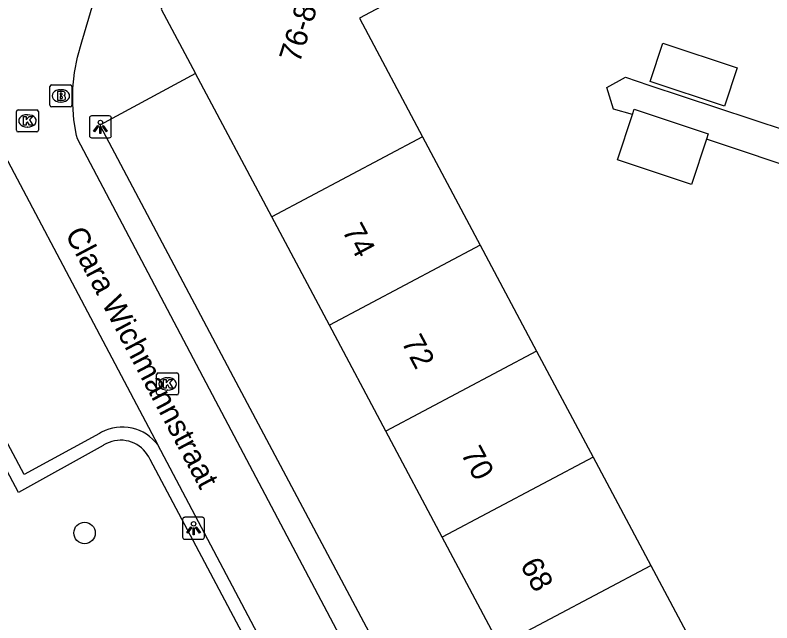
# Model space of a CAD drawing. Extents: x 160304 to 160954, y 383686 to 384161.
# Drawn here: x 160598.37 to 160632.85, y 383834.88 to 383862.58 of the extents above; entities that cross this region are included whole.
import ezdxf

# ---------------------------------------------------------------- set-up
doc = ezdxf.new("R2010")
doc.units = 0
for name, color, linetype in [('IMGEO_Boom', 7, 'Continuous'), ('IMGEO_Brandkraan', 7, 'Continuous'), ('IMGEO_Kolk', 7, 'Continuous'), ('IMGEO_Lichtpunt', 7, 'Continuous'), ('IMGEO_Openbare_ruimte_label', 7, 'Continuous'), ('IMGEO_Pand', 7, 'Continuous'), ('IMGEO_Pand_nummerreeks', 7, 'Continuous'), ('IMGEO_Rijbaan_lokaal_open', 7, 'Continuous'), ('IMGEO_Voetpad_open', 7, 'Continuous')]:
    doc.layers.add(name, color=color, linetype=linetype)

msp = doc.modelspace()

# ---------------------------------------------------------------- linework, layer by layer
at = {"layer": 'IMGEO_Boom'}
msp.add_circle((160601.533, 383838.982), 0.489, dxfattribs=at)
at = {"layer": 'IMGEO_Brandkraan'}
for p, q in [((160599.952, 383858.474), (160599.952, 383859.326)), ((160600.027, 383859.4), (160600.879, 383859.4)), ((160600.953, 383859.326), (160600.953, 383858.474)), ((160600.44, 383859.18), (160600.465, 383859.18)), ((160600.463, 383858.62), (160600.438, 383858.62)), ((160600.879, 383858.4), (160600.027, 383858.4))]:
    msp.add_line(p, q, dxfattribs=at)
for points in [[(160599.952, 383858.474), (160599.952, 383859.326)], [(160600.027, 383859.4), (160600.879, 383859.4)], [(160600.953, 383859.326), (160600.953, 383858.474)], [(160600.3, 383859.1), (160600.3, 383858.7), (160600.513, 383858.7)], [(160600.531, 383859.1), (160600.3, 383859.1)], [(160600.479, 383859.019), (160600.425, 383859.019), (160600.425, 383858.943)], [(160600.425, 383858.943), (160600.478, 383858.943)], [(160600.487, 383858.867), (160600.425, 383858.867), (160600.425, 383858.786)], [(160600.425, 383858.786), (160600.487, 383858.786)], [(160600.879, 383858.4), (160600.027, 383858.4)]]:
    msp.add_lwpolyline(points, dxfattribs=at)
for centre, radius, start, end in [((160600.029, 383859.324), 0.0765, 91.552, 178.448), ((160600.029, 383859.324), 0.0765, 91.552, 178.448), ((160600.877, 383859.324), 0.0765, 1.552, 88.448), ((160600.877, 383859.324), 0.0765, 1.552, 88.448), ((160600.48, 383858.981), 0.0379, 267.8285, 90.9355), ((160600.535, 383858.955), 0.145, 59.4692, 91.5367), ((160600.56, 383859.002), 0.0922, 285.5137, 58.1501), ((160600.565, 383858.81), 0.105, 301.3115, 78.989), ((160600.488, 383858.826), 0.0404, 269.8759, 90.5077), ((160600.519, 383858.951), 0.251, 268.6676, 293.5347), ((160600.029, 383858.476), 0.0765, 181.552, 268.448), ((160600.029, 383858.476), 0.0765, 181.552, 268.448), ((160600.877, 383858.476), 0.0765, 271.552, 358.448), ((160600.877, 383858.476), 0.0765, 271.552, 358.448)]:
    msp.add_arc(centre, radius, start, end, dxfattribs=at)
for centre, major_axis, ratio, start_param, end_param in [((160600.439, 383858.9), (-0.387, 0.002), 0.722429, 4.712389, 7.853982), ((160600.464, 383858.9), (-0.39, 0.002), 0.717154, 1.570796, 4.712389)]:
    msp.add_ellipse(centre, major_axis=major_axis, ratio=ratio, start_param=start_param, end_param=end_param, dxfattribs=at)
at = {"layer": 'IMGEO_Kolk'}
for p, q in [((160598.506, 383858.258), (160599.358, 383858.258)), ((160598.431, 383857.332), (160598.431, 383858.184)), ((160598.919, 383858.038), (160598.944, 383858.038)), ((160599.432, 383858.184), (160599.432, 383857.332)), ((160599.358, 383857.258), (160598.506, 383857.258)), ((160598.942, 383857.478), (160598.917, 383857.478)), ((160604.815, 383845.348), (160604.815, 383846.2)), ((160604.89, 383846.274), (160605.742, 383846.274)), ((160605.816, 383846.2), (160605.816, 383845.348)), ((160605.303, 383846.054), (160605.328, 383846.054)), ((160605.326, 383845.494), (160605.301, 383845.494)), ((160605.742, 383845.274), (160604.89, 383845.274))]:
    msp.add_line(p, q, dxfattribs=at)
for points in [[(160598.506, 383858.258), (160599.358, 383858.258)], [(160598.431, 383857.332), (160598.431, 383858.184)], [(160598.752, 383857.958), (160598.875, 383857.958), (160598.875, 383857.807), (160599.005, 383857.958), (160599.169, 383857.958), (160599.023, 383857.807), (160599.176, 383857.558), (160599.024, 383857.558), (160598.939, 383857.722), (160598.875, 383857.655), (160598.875, 383857.558), (160598.752, 383857.558), (160598.752, 383857.958)], [(160599.432, 383858.184), (160599.432, 383857.332)], [(160599.358, 383857.258), (160598.506, 383857.258)], [(160604.815, 383845.348), (160604.815, 383846.2)], [(160604.89, 383846.274), (160605.742, 383846.274)], [(160605.816, 383846.2), (160605.816, 383845.348)], [(160605.136, 383845.974), (160605.259, 383845.974), (160605.259, 383845.823), (160605.389, 383845.974), (160605.553, 383845.974), (160605.407, 383845.823), (160605.56, 383845.574), (160605.408, 383845.574), (160605.323, 383845.738), (160605.259, 383845.671), (160605.259, 383845.574), (160605.136, 383845.574), (160605.136, 383845.974)], [(160605.742, 383845.274), (160604.89, 383845.274)]]:
    msp.add_lwpolyline(points, dxfattribs=at)
for centre, start, end in [((160598.508, 383858.182), 91.552, 178.448), ((160598.508, 383858.182), 91.552, 178.448), ((160599.356, 383858.182), 1.552, 88.448), ((160599.356, 383858.182), 1.552, 88.448), ((160598.508, 383857.334), 181.552, 268.448), ((160598.508, 383857.334), 181.552, 268.448), ((160599.356, 383857.334), 271.552, 358.448), ((160599.356, 383857.334), 271.552, 358.448), ((160604.892, 383846.198), 91.552, 178.448), ((160604.892, 383846.198), 91.552, 178.448), ((160605.74, 383846.198), 1.552, 88.448), ((160605.74, 383846.198), 1.552, 88.448), ((160604.892, 383845.35), 181.552, 268.448), ((160604.892, 383845.35), 181.552, 268.448), ((160605.74, 383845.35), 271.552, 358.448), ((160605.74, 383845.35), 271.552, 358.448)]:
    msp.add_arc(centre, 0.0765, start, end, dxfattribs=at)
for centre, major_axis, ratio, start_param, end_param in [((160598.918, 383857.758), (-0.387, 0.002), 0.722429, 4.712389, 7.853982), ((160598.943, 383857.758), (-0.39, 0.002), 0.717154, 1.570796, 4.712389), ((160605.302, 383845.774), (-0.387, 0.002), 0.722429, 4.712389, 7.853982), ((160605.327, 383845.774), (-0.39, 0.002), 0.717154, 1.570796, 4.712389)]:
    msp.add_ellipse(centre, major_axis=major_axis, ratio=ratio, start_param=start_param, end_param=end_param, dxfattribs=at)
at = {"layer": 'IMGEO_Lichtpunt'}
for p, q in [((160601.757, 383857.89), (160601.757, 383857.083)), ((160601.757, 383857.89), (160601.757, 383857.083)), ((160602.659, 383857.985), (160601.851, 383857.985)), ((160602.659, 383857.985), (160601.851, 383857.985)), ((160602.753, 383857.083), (160602.753, 383857.89)), ((160602.753, 383857.083), (160602.753, 383857.89)), ((160601.851, 383856.989), (160602.659, 383856.989)), ((160601.851, 383856.989), (160602.659, 383856.989)), ((160606.001, 383839.599), (160606.001, 383838.792)), ((160606.001, 383839.599), (160606.001, 383838.792)), ((160606.903, 383839.694), (160606.095, 383839.694)), ((160606.903, 383839.694), (160606.095, 383839.694)), ((160606.997, 383838.792), (160606.997, 383839.599)), ((160606.997, 383838.792), (160606.997, 383839.599)), ((160606.095, 383838.698), (160606.903, 383838.698)), ((160606.095, 383838.698), (160606.903, 383838.698))]:
    msp.add_line(p, q, dxfattribs=at)
for points in [[(160602.131, 383857.554), (160602.17, 383857.526), (160601.982, 383857.264), (160601.944, 383857.291), (160602.131, 383857.554)], [(160602.343, 383857.526), (160602.381, 383857.553), (160602.568, 383857.291), (160602.529, 383857.263), (160602.343, 383857.526)], [(160602.233, 383857.506), (160602.28, 383857.506), (160602.28, 383857.184), (160602.233, 383857.184), (160602.233, 383857.506)], [(160606.375, 383839.263), (160606.414, 383839.235), (160606.226, 383838.973), (160606.188, 383839), (160606.375, 383839.263)], [(160606.587, 383839.235), (160606.625, 383839.262), (160606.812, 383839), (160606.773, 383838.972), (160606.587, 383839.235)], [(160606.477, 383839.215), (160606.524, 383839.215), (160606.524, 383838.893), (160606.477, 383838.893), (160606.477, 383839.215)]]:
    msp.add_lwpolyline(points, dxfattribs=at)
for centre in [(160602.256, 383857.688), (160606.5, 383839.397)]:
    msp.add_circle(centre, 0.0994, dxfattribs=at)
for centre, start, end in [((160601.851, 383857.89), 90, 180), ((160601.851, 383857.89), 90, 180), ((160602.659, 383857.89), 0, 90), ((160602.659, 383857.89), 0, 90), ((160601.851, 383857.083), 180, 270), ((160601.851, 383857.083), 180, 270), ((160602.659, 383857.083), 270, 0), ((160602.659, 383857.083), 270, 360), ((160606.095, 383839.599), 90, 180), ((160606.095, 383839.599), 90, 180), ((160606.903, 383839.599), 0, 90), ((160606.903, 383839.599), 0, 90), ((160606.095, 383838.792), 180, 270), ((160606.095, 383838.792), 180, 270), ((160606.903, 383838.792), 270, 0), ((160606.903, 383838.792), 270, 360)]:
    msp.add_arc(centre, 0.0946, start, end, dxfattribs=at)
at = {"layer": 'IMGEO_Pand'}
for points in [[(160609.342, 383868.714), (160606.323, 383867.106), (160605.944, 383865.863), (160605.42, 383864.141), (160605.024, 383862.845), (160606.586, 383859.913)], [(160619.961, 383865.579), (160614.056, 383862.434), (160616.932, 383857.033)], [(160627.302, 383859.548), (160627.881, 383861.3), (160631.275, 383860.176), (160630.695, 383858.425), (160627.302, 383859.548)], [(160610.063, 383853.384), (160606.586, 383859.913)], [(160626.502, 383858.047), (160626.583, 383858.29), (160629.953, 383857.167), (160629.872, 383856.923)], [(160629.872, 383856.923), (160629.186, 383854.868), (160625.817, 383855.991), (160626.502, 383858.047)], [(160616.932, 383857.033), (160610.063, 383853.384)], [(160616.932, 383857.033), (160619.558, 383852.103)], [(160612.692, 383848.446), (160610.063, 383853.384)], [(160619.558, 383852.103), (160612.692, 383848.446)], [(160619.558, 383852.103), (160622.131, 383847.273)], [(160615.265, 383843.616), (160612.692, 383848.446)], [(160622.131, 383847.273), (160615.265, 383843.616)], [(160622.131, 383847.273), (160624.703, 383842.443)], [(160617.836, 383838.787), (160615.265, 383843.616)], [(160624.703, 383842.443), (160617.836, 383838.787)], [(160624.703, 383842.443), (160627.335, 383837.501)], [(160620.464, 383833.854), (160617.836, 383838.787)], [(160620.464, 383833.854), (160627.335, 383837.501)], [(160627.335, 383837.501), (160630.447, 383831.658)]]:
    msp.add_lwpolyline(points, dxfattribs=at)
at = {"layer": 'IMGEO_Rijbaan_lokaal_open'}
for points in [[(160614.718, 383831.355), (160607.23, 383845.532), (160601.204, 383856.942), (160601.168, 383857.1), (160601.049, 383857.809), (160600.993, 383858.527), (160601.001, 383859.246), (160601.074, 383859.962), (160601.21, 383860.668), (160601.409, 383861.36), (160602.642, 383865.533), (160602.872, 383866.499), (160603.015, 383867.482), (160603.07, 383868.474), (160603.036, 383869.467), (160602.913, 383870.453), (160602.702, 383871.424), (160602.406, 383872.372), (160602.026, 383873.29), (160601.566, 383874.171)], [(160594.822, 383861.978), (160604.871, 383842.991)], [(160611.835, 383829.832), (160604.871, 383842.991)]]:
    msp.add_lwpolyline(points, dxfattribs=at)
at = {"layer": 'IMGEO_Voetpad_open'}
for points in [[(160604.871, 383842.991), (160604.758, 383843.131), (160604.634, 383843.259), (160604.498, 383843.377), (160604.353, 383843.481), (160604.199, 383843.573), (160604.037, 383843.65), (160603.869, 383843.712), (160603.696, 383843.759), (160603.52, 383843.791), (160603.341, 383843.807), (160603.162, 383843.806), (160602.983, 383843.79), (160602.807, 383843.757), (160602.634, 383843.71), (160602.467, 383843.646), (160602.305, 383843.568), (160602.207, 383843.512), (160598.777, 383841.649), (160589.436, 383859.161), (160594.822, 383861.978)], [(160606.586, 383859.913), (160602.222, 383857.561), (160608.312, 383846.103), (160626.241, 383812.373), (160626.527, 383811.938), (160626.85, 383811.531), (160627.209, 383811.154), (160627.6, 383810.811), (160628.02, 383810.504), (160628.465, 383810.236), (160628.933, 383810.009), (160629.419, 383809.824), (160629.92, 383809.684), (160630.04, 383809.657), (160645.643, 383804.913)], [(160626.502, 383858.047), (160625.638, 383858.3), (160625.326, 383859.284), (160626.186, 383859.758), (160627.249, 383859.386), (160635.069, 383856.802)], [(160634.642, 383855.331), (160629.872, 383856.923)], [(160619.328, 383814.427), (160604.518, 383842.331), (160604.46, 383842.449), (160604.391, 383842.561), (160604.313, 383842.666), (160604.225, 383842.764), (160604.129, 383842.854), (160604.025, 383842.935), (160603.915, 383843.007), (160603.799, 383843.068), (160603.677, 383843.118), (160603.552, 383843.158), (160603.424, 383843.186), (160603.293, 383843.203), (160603.162, 383843.207), (160603.031, 383843.201), (160602.901, 383843.182), (160602.773, 383843.152), (160602.648, 383843.11), (160602.527, 383843.058), (160602.412, 383842.995), (160602.375, 383842.972), (160598.521, 383840.826), (160593.955, 383849.41)]]:
    msp.add_lwpolyline(points, dxfattribs=at)

# ---------------------------------------------------------------- texts
at = {"layer": 'IMGEO_Openbare_ruimte_label'}
msp.add_text('Clara Wichmannstraat', height=1, rotation=297.8973, dxfattribs=at).set_placement((160600.624, 383852.606))
at = {"layer": 'IMGEO_Pand_nummerreeks'}
for s, rotation, p in [('76-86', 72.2156, (160611.328, 383860.355)), ('74', 298.0372, (160613.25, 383852.76)), ('72', 298.0372, (160615.952, 383847.686)), ('70', 298.0372, (160618.658, 383842.604)), ('68', 298.0372, (160621.362, 383837.528))]:
    msp.add_text(s, height=1, rotation=rotation, dxfattribs=at).set_placement(p)

doc.saveas('drawing.dxf')
